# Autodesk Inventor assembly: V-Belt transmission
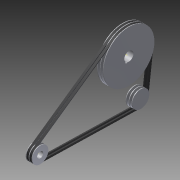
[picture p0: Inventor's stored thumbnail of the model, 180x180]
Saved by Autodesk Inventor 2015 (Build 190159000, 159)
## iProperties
Created: 2007-02
Part Number: V-Belt transmission
Document SubType Name: Assembly
Designer: Autodesk, Inc.
Mass: 6091.08 g
Surface Area: 3668.86 cm^2
Volume: 2424.75 cm^3
Density: 2.51205 g/cm^3
ClientObjectVersion: 1
Author: Autodesk, Inc.
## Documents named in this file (5)
- C:\Users\Public\Documents\Autodesk\Inventor 2015\Samples\Models\Assemblies\Blower\Blower\Design Accelerator\V-Belt transmission1.iam
- C:\Users\Public\Documents\Autodesk\Inventor 2015\Samples\Models\Assemblies\Blower\Blower\Design Accelerator\V-Belt1.ipt
- C:\Users\Public\Documents\Autodesk\Inventor 2015\Samples\Models\Assemblies\Blower\Blower\Design Accelerator\Grooved Pulley31.ipt
- C:\Users\Public\Documents\Autodesk\Inventor 2015\Samples\Models\Assemblies\Blower\Blower\Design Accelerator\Grooved Pulley41.ipt
- C:\Users\Public\Documents\Autodesk\Inventor 2015\Samples\Models\Assemblies\Blower\Blower\Design Accelerator\Grooved Pulley51.ipt
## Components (5 placed, 4 different names)
1. P - 001 - Aluminum-6061:3 — Flush:1, Rotation:1, Rotation:2
2. P- 002 - Aluminum-6061:4 — Flush:3, Rotation:2
3. P - 003 - Aluminum-6061:5 — Flush:2, Rotation:1
4. VB - 002:1 — Flush:1, Flush:2, Flush:3
5. VB - 002:2
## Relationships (5: Flush 3, RelateRotation 2)
- Flush:1: P - 001 - Aluminum-6061:3 ↔ VB - 002:1
- Flush:2: P - 003 - Aluminum-6061:5 ↔ VB - 002:1
- Rotation:1 [RelateRotation]: P - 001 - Aluminum-6061:3 ↔ P - 003 - Aluminum-6061:5
- Flush:3: P- 002 - Aluminum-6061:4 ↔ VB - 002:1
- Rotation:2 [RelateRotation]: P - 001 - Aluminum-6061:3 ↔ P- 002 - Aluminum-6061:4
